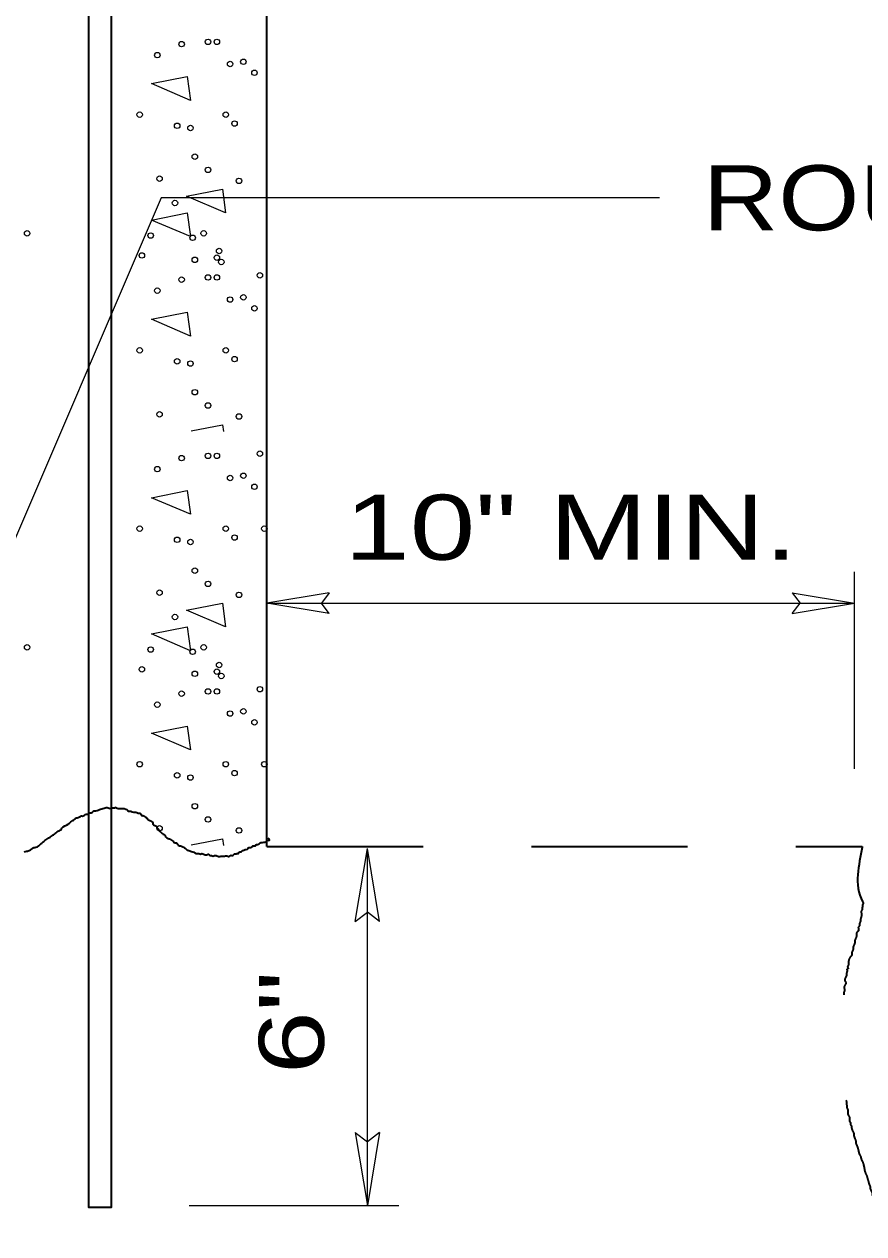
# Model space of a CAD drawing. Extents: x 2.21 to 9.21, y 11.59 to 21.05.
# Drawn here: x 4.703 to 5.477, y 17.546 to 18.662 of the extents above; entities that cross this region are included whole.
import ezdxf
from ezdxf.enums import TextEntityAlignment as Align

# ---------------------------------------------------------------- set-up
doc = ezdxf.new("R2010")
doc.units = 0
doc.header["$LTSCALE"] = 0.024
doc.linetypes.add('LONG_DASHED', pattern=[7.5, 6, -1.5])
for name, color, linetype, lineweight in [('1', 7, 'Continuous', 35), ('10', 7, 'Continuous', 13), ('12', 7, 'Continuous', 53), ('6', 7, 'Continuous', 13)]:
    doc.layers.add(name, color=color, linetype=linetype, lineweight=lineweight)

msp = doc.modelspace()

# ---------------------------------------------------------------- linework, layer by layer
at = {"layer": '1'}
msp.add_line((4.92667, 17.90333), (4.92667, 19.96033), dxfattribs=at)
at = {"layer": '1', "linetype": 'LONG_DASHED'}
msp.add_line((4.92667, 17.90333), (5.47583, 17.90333), dxfattribs=at)
at = {"layer": '1'}
msp.add_lwpolyline([(4.78283, 19.512), (4.78283, 17.57083), (4.78283, 17.57), (4.76217, 17.57), (4.76217, 19.51117)], dxfattribs=at)
for points in [[(4.7025, 17.89833), (4.70483, 17.89883), (4.70783, 17.89983), (4.70917, 17.90067), (4.71167, 17.90217), (4.7135, 17.9025), (4.71833, 17.90583), (4.72067, 17.90783), (4.7245, 17.91067), (4.726, 17.9115), (4.727, 17.912), (4.72883, 17.9135), (4.73217, 17.91583), (4.73317, 17.91683), (4.7365, 17.91867), (4.7375, 17.92017), (4.74317, 17.92383), (4.74567, 17.92583), (4.7475, 17.92717), (4.749, 17.92817), (4.7495, 17.92867), (4.75233, 17.93), (4.75383, 17.9305), (4.75567, 17.93133), (4.75717, 17.93133), (4.7585, 17.93233), (4.759, 17.93283), (4.761, 17.93317), (4.76233, 17.93367), (4.76283, 17.93417), (4.76433, 17.93417), (4.76717, 17.936), (4.76867, 17.936), (4.771, 17.93683), (4.77533, 17.93817), (4.77917, 17.93917), (4.781, 17.9385), (4.783, 17.9385), (4.78433, 17.939), (4.78633, 17.939), (4.78683, 17.93933), (4.78783, 17.93883), (4.79067, 17.93833), (4.79633, 17.93767), (4.79783, 17.93667), (4.79833, 17.93617), (4.80117, 17.93567), (4.8035, 17.935), (4.805, 17.935), (4.8065, 17.9345), (4.80783, 17.934), (4.80933, 17.934), (4.81067, 17.93283), (4.81167, 17.93133), (4.81217, 17.93183), (4.81367, 17.93083), (4.8155, 17.92983), (4.8165, 17.92833), (4.818, 17.92733), (4.82133, 17.92483), (4.82133, 17.92383), (4.82267, 17.92283), (4.82467, 17.92167), (4.8255, 17.92017), (4.827, 17.91867), (4.828, 17.91717), (4.83083, 17.91467), (4.83233, 17.91367), (4.83283, 17.91317), (4.83417, 17.91117), (4.837, 17.91017), (4.8385, 17.90917), (4.84033, 17.90767), (4.84183, 17.9065), (4.84333, 17.9065), (4.84433, 17.905), (4.84467, 17.9045), (4.84767, 17.9035), (4.8505, 17.902), (4.85183, 17.901), (4.85233, 17.90033), (4.85533, 17.89933), (4.85617, 17.89883), (4.85817, 17.89833), (4.86233, 17.89667), (4.86383, 17.89667), (4.86533, 17.89617), (4.86667, 17.89667), (4.86817, 17.89617), (4.871, 17.8955), (4.8725, 17.896), (4.874, 17.895), (4.87533, 17.895), (4.87683, 17.89433), (4.87817, 17.89483), (4.87967, 17.89483), (4.88117, 17.89433)], [(4.88117, 17.89433), (4.8825, 17.89383), (4.884, 17.89417), (4.88683, 17.89417), (4.88833, 17.8945), (4.88967, 17.8945), (4.89117, 17.894), (4.8925, 17.8945), (4.893, 17.895), (4.894, 17.895), (4.8955, 17.89533), (4.89683, 17.89633), (4.89833, 17.89633), (4.89933, 17.89683), (4.90033, 17.89667), (4.90067, 17.89767), (4.90167, 17.89817), (4.90317, 17.89867), (4.90367, 17.89917), (4.9045, 17.8995), (4.906, 17.9), (4.9065, 17.9005), (4.9075, 17.9005), (4.90933, 17.90133), (4.90933, 17.90183), (4.91083, 17.90233), (4.91217, 17.90233), (4.91367, 17.90367), (4.91517, 17.90367), (4.9165, 17.90417), (4.9165, 17.90467), (4.918, 17.90517), (4.9195, 17.9055), (4.91983, 17.906), (4.92267, 17.907), (4.92467, 17.90733), (4.92617, 17.90783), (4.92667, 17.90883), (4.9275, 17.90883), (4.929, 17.90917), (4.9275, 17.91067)]]:
    msp.add_spline(points, degree=3, dxfattribs=at)
at = {"layer": '10'}
for p, q in [((4.829, 18.50167), (4.586, 17.935)), ((5.28883, 18.50167), (4.829, 18.50167)), ((5.46883, 17.97483), (5.46883, 18.1565)), ((4.98417, 18.13733), (4.92667, 18.12783)), ((4.98417, 18.13733), (4.977, 18.12783)), ((5.41117, 18.13733), (5.46883, 18.12783)), ((5.41117, 18.13733), (5.4185, 18.12783)), ((4.92667, 18.12783), (5.46883, 18.12783)), ((4.98417, 18.11817), (4.92667, 18.12783)), ((4.98417, 18.11817), (4.977, 18.12783)), ((5.41117, 18.11817), (5.46883, 18.12783)), ((5.41117, 18.11817), (5.4185, 18.12783)), ((5.008, 17.834), (5.01933, 17.90133)), ((5.01933, 17.57183), (5.01933, 17.90133)), ((5.0305, 17.834), (5.01933, 17.90133)), ((5.008, 17.834), (5.01933, 17.8425)), ((5.0305, 17.834), (5.01933, 17.8425)), ((5.008, 17.63917), (5.01933, 17.57183)), ((5.008, 17.63917), (5.01933, 17.63067)), ((5.0305, 17.63917), (5.01933, 17.57183)), ((5.0305, 17.63917), (5.01933, 17.63067)), ((4.85483, 17.57183), (5.04817, 17.57183))]:
    msp.add_line(p, q, dxfattribs=at)
at = {"layer": '10', "linetype": 'LONG_DASHED', "lineweight": 35}
for points in [[(5.47583, 17.90333), (5.47567, 17.90233), (5.47617, 17.85233), (5.47667, 17.85083), (5.47617, 17.8495), (5.47617, 17.848), (5.47567, 17.8465), (5.47567, 17.845), (5.47517, 17.844), (5.47517, 17.83967), (5.47483, 17.83817), (5.47433, 17.83617), (5.47433, 17.83483), (5.47333, 17.83183), (5.47333, 17.83033), (5.47233, 17.82883), (5.47233, 17.8255), (5.47083, 17.824), (5.4705, 17.82067), (5.469, 17.81617), (5.469, 17.81483), (5.468, 17.81183), (5.4675, 17.81033), (5.4675, 17.80883), (5.46667, 17.8065), (5.46617, 17.8045), (5.46617, 17.803), (5.46517, 17.80167), (5.46317, 17.79633), (5.46283, 17.79333), (5.46233, 17.79183), (5.46283, 17.7905), (5.46183, 17.79), (5.46183, 17.789), (5.46133, 17.786), (5.46133, 17.7845), (5.46083, 17.78317), (5.45983, 17.77917), (5.46083, 17.77767), (5.45933, 17.77433), (5.45933, 17.76983), (5.45883, 17.7685), (5.45883, 17.765), (5.458, 17.762), (5.458, 17.75667), (5.457, 17.75383), (5.456, 17.75183), (5.456, 17.74783), (5.4565, 17.7465), (5.4555, 17.7425), (5.4555, 17.741), (5.455, 17.7395), (5.455, 17.73567), (5.45467, 17.73417), (5.45417, 17.73183), (5.45367, 17.72833), (5.45367, 17.72483), (5.45417, 17.7235), (5.45417, 17.722), (5.45367, 17.72), (5.45367, 17.7185), (5.45417, 17.717), (5.45367, 17.7155), (5.45467, 17.71267), (5.45467, 17.71117), (5.455, 17.70917), (5.45467, 17.70767), (5.45467, 17.70483), (5.455, 17.70183), (5.4555, 17.70033), (5.4555, 17.69883), (5.4555, 17.696), (5.456, 17.69433), (5.456, 17.693), (5.4565, 17.69), (5.457, 17.6885), (5.457, 17.687), (5.4575, 17.6855), (5.45833, 17.6835), (5.45833, 17.68067), (5.45933, 17.67767), (5.45933, 17.67617), (5.45983, 17.67367), (5.46033, 17.67217), (5.46033, 17.67083), (5.46133, 17.66733), (5.46133, 17.66533), (5.46167, 17.66383), (5.46167, 17.66233), (5.46217, 17.661), (5.46267, 17.659), (5.46267, 17.656), (5.46417, 17.653), (5.46417, 17.6495), (5.465, 17.64817), (5.465, 17.64667), (5.466, 17.64517)], [(5.466, 17.64517), (5.466, 17.64367), (5.467, 17.64067), (5.4675, 17.63967), (5.468, 17.63817), (5.468, 17.63667), (5.4685, 17.63517), (5.46883, 17.63417), (5.46983, 17.63133), (5.46983, 17.62983), (5.47083, 17.62733), (5.47183, 17.62433), (5.47267, 17.621), (5.47317, 17.61933), (5.47417, 17.6175), (5.47517, 17.614), (5.476, 17.6125), (5.477, 17.6095), (5.4775, 17.6075), (5.478, 17.6045), (5.4785, 17.60267), (5.48033, 17.59817), (5.48083, 17.59617), (5.48133, 17.59467), (5.48183, 17.59267), (5.48233, 17.59117), (5.48317, 17.58883), (5.48317, 17.58783), (5.48367, 17.58633), (5.48467, 17.58433), (5.48517, 17.58283), (5.48517, 17.58133), (5.48617, 17.57983), (5.48617, 17.57833), (5.488, 17.5725), (5.489, 17.57), (5.49, 17.5675), (5.49, 17.5655), (5.4905, 17.564), (5.49083, 17.562), (5.49133, 17.5605), (5.49133, 17.55917), (5.49183, 17.55667), (5.49283, 17.55517), (5.49283, 17.55317), (5.49333, 17.54967), (5.49467, 17.54767), (5.49467, 17.54633), (5.49517, 17.54483), (5.49567, 17.54133), (5.49617, 17.54033), (5.49667, 17.53733), (5.49717, 17.53583), (5.49767, 17.5325), (5.4985, 17.531), (5.4985, 17.5295), (5.499, 17.527), (5.5, 17.524), (5.5, 17.52267), (5.50133, 17.51817), (5.50133, 17.51617), (5.50183, 17.51517), (5.50183, 17.51417), (5.50233, 17.51267), (5.50233, 17.51117), (5.50283, 17.50933), (5.50333, 17.50833), (5.50283, 17.50783), (5.50383, 17.50633), (5.50383, 17.50483), (5.50433, 17.50333), (5.50433, 17.50183), (5.50517, 17.49883), (5.50483, 17.4975), (5.50567, 17.4945), (5.50617, 17.4935), (5.50617, 17.4925), (5.50667, 17.491), (5.50667, 17.48317), (5.50717, 17.48167), (5.50717, 17.46983), (5.50767, 17.4685), (5.50767, 17.4625), (5.508, 17.461), (5.508, 17.45267), (5.5085, 17.45117), (5.5085, 17.44783), (5.508, 17.44483), (5.5085, 17.44333), (5.5085, 17.44033), (5.5085, 17.4325), (5.508, 17.43117), (5.5085, 17.42967), (5.5085, 17.42817), (5.508, 17.42667), (5.508, 17.42467), (5.50767, 17.42333)]]:
    msp.add_spline(points, degree=3, dxfattribs=at)
at = {"layer": '6'}
for points in [[(4.82, 18.607), (4.853, 18.6135), (4.856, 18.5915)], [(4.8525, 18.50317), (4.88567, 18.5095), (4.8885, 18.48767)], [(4.82, 18.48117), (4.853, 18.48767), (4.856, 18.46583)], [(4.82, 18.38967), (4.853, 18.39617), (4.856, 18.37417)], [(4.82, 18.225), (4.853, 18.2315), (4.856, 18.20967)], [(4.8525, 18.12117), (4.88567, 18.12767), (4.8885, 18.10583)], [(4.82, 18.09933), (4.853, 18.10583), (4.856, 18.08383)], [(4.82, 18.00767), (4.853, 18.01417), (4.856, 17.99233)]]:
    msp.add_lwpolyline(points, close=True, dxfattribs=at)
for points in [[(4.85683, 18.28667), (4.88567, 18.29217), (4.8865, 18.28617)], [(4.85683, 17.90467), (4.88567, 17.91033), (4.8865, 17.90417)]]:
    msp.add_lwpolyline(points, dxfattribs=at)
for centre in [(4.84789, 18.64348), (4.8723, 18.64553), (4.88046, 18.64553), (4.82549, 18.63332), (4.89266, 18.62516), (4.9049, 18.6272), (4.91506, 18.61704), (4.80921, 18.57835), (4.84381, 18.56815), (4.88862, 18.57835), (4.89674, 18.57019), (4.85601, 18.56611), (4.86009, 18.53967), (4.8723, 18.52743), (4.82753, 18.5193), (4.90082, 18.51726), (4.84177, 18.4969), (4.70535, 18.4689), (4.86826, 18.4689), (4.81937, 18.46686), (4.85805, 18.46482), (4.81125, 18.44853), (4.88046, 18.44649), (4.8825, 18.45261), (4.86009, 18.44445), (4.88454, 18.44241), (4.84789, 18.42613), (4.8723, 18.42817), (4.88046, 18.42817), (4.9201, 18.43021), (4.82549, 18.41597), (4.89266, 18.40781), (4.9049, 18.40985), (4.91506, 18.39969), (4.80921, 18.361), (4.88862, 18.361), (4.84381, 18.3508), (4.85601, 18.34876), (4.89674, 18.35284), (4.86009, 18.32231), (4.82753, 18.30195), (4.8723, 18.31007), (4.90082, 18.29991), (4.84789, 18.26154), (4.8723, 18.26358), (4.88046, 18.26358), (4.9201, 18.26562), (4.82549, 18.25138), (4.9049, 18.24526), (4.89266, 18.24322), (4.91506, 18.2351), (4.80921, 18.19641), (4.88862, 18.19641), (4.92418, 18.19641), (4.84381, 18.18621), (4.85601, 18.18417), (4.89674, 18.18825), (4.86009, 18.15773), (4.8723, 18.14549), (4.82753, 18.13736), (4.90082, 18.13532), (4.84177, 18.11496), (4.70535, 18.08696), (4.81937, 18.08492), (4.85805, 18.08288), (4.86826, 18.08696), (4.81125, 18.06659), (4.8825, 18.07067), (4.86009, 18.06251), (4.88046, 18.06455), (4.88454, 18.06047), (4.84789, 18.04419), (4.8723, 18.04623), (4.88046, 18.04623), (4.9201, 18.04827), (4.82549, 18.03403), (4.89266, 18.02587), (4.9049, 18.02791), (4.91506, 18.01774), (4.80921, 17.97906), (4.88862, 17.97906), (4.92418, 17.97906), (4.84381, 17.96886), (4.85601, 17.96682), (4.89674, 17.9709), (4.86009, 17.94037), (4.8723, 17.92813), (4.82753, 17.92001), (4.90082, 17.91797)]:
    msp.add_circle(centre, 0.00252, dxfattribs=at)

# ---------------------------------------------------------------- texts
at = {"layer": '12', "width": 1.2}
msp.add_text('ROUGHEN EXISTING PAVEMENT', height=0.06001, dxfattribs=at).set_placement((5.32883, 18.47167))
at = {"layer": '12', "width": 1.35}
msp.add_text('10" MIN.', height=0.06001, dxfattribs=at).set_placement((5.20708, 18.16775), align=Align.CENTER)
at = {"layer": '12', "width": 1.3}
msp.add_text('6"', height=0.06001, rotation=90, dxfattribs=at).set_placement((4.97917, 17.74075), align=Align.CENTER)

doc.saveas('drawing.dxf')
